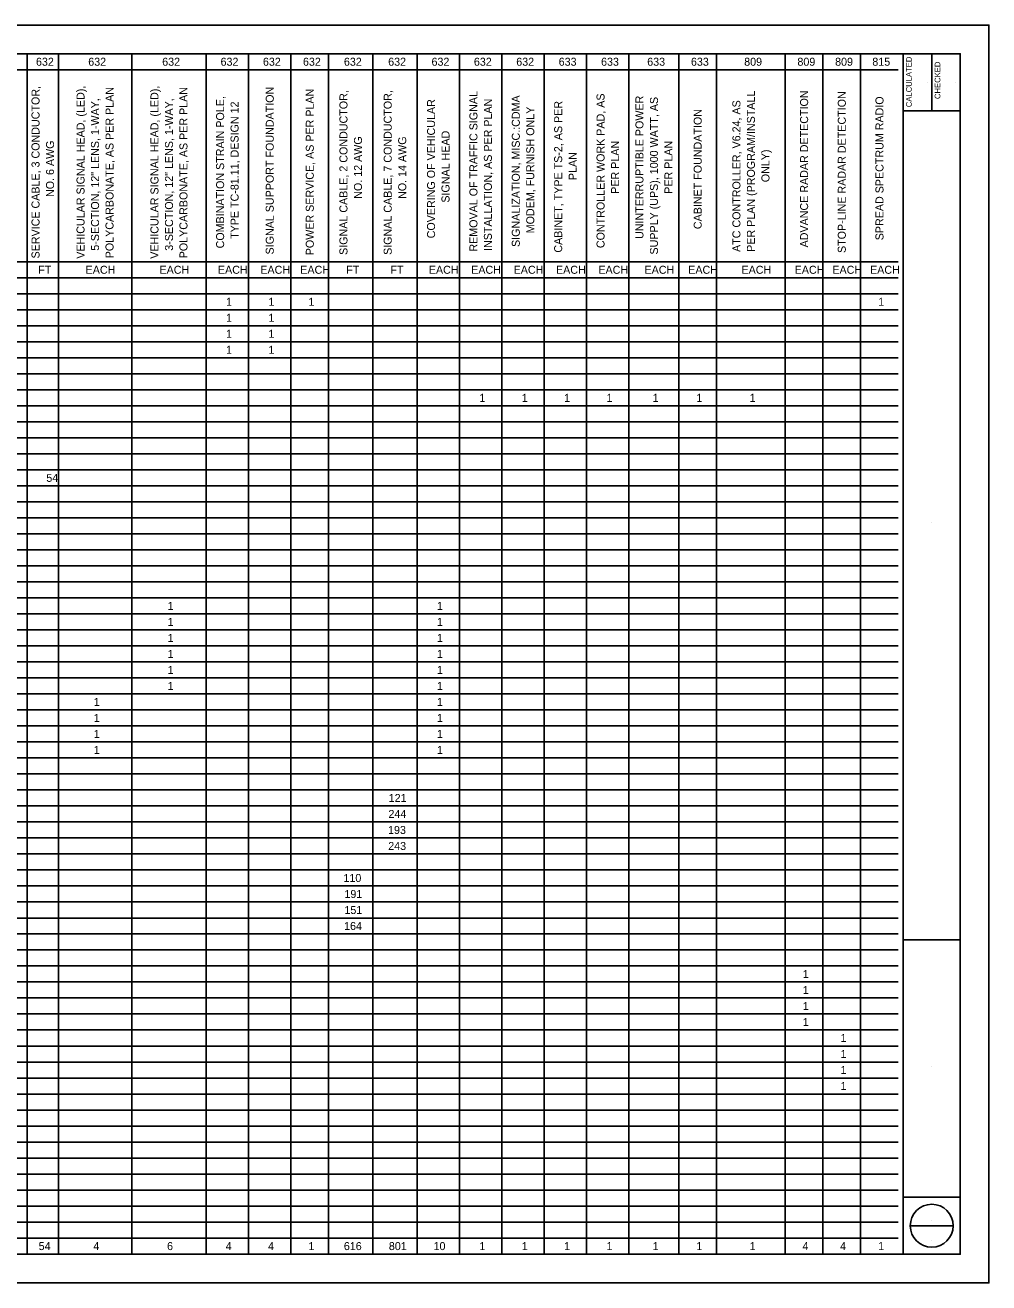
# Model space of a CAD drawing. Extents: x 43.5 to 77.5, y 34.1 to 56.1.
# Drawn here: x 60.61 to 77.46, y 34.09 to 56.09 of the extents above; entities that cross this region are included whole.
import ezdxf

# ---------------------------------------------------------------- set-up
doc = ezdxf.new("R2010")
doc.units = 0
for name, color, linetype in [('SH_Border', 7, 'Continuous'), ('SH_Cut_Line', 7, 'Continuous'), ('SH_Data', 7, 'Continuous'), ('SH_Text', 7, 'Continuous')]:
    doc.layers.add(name, color=color, linetype=linetype)

msp = doc.modelspace()

# ---------------------------------------------------------------- linework, layer by layer
at = {"layer": 'SH_Border'}
for p, q in [((45.459, 55.586), (75.875, 55.586)), ((60.642, 55.586), (60.642, 34.589)), ((61.186, 55.586), (61.186, 34.589)), ((62.47, 55.586), (62.47, 34.589)), ((63.771, 55.586), (63.771, 34.589)), ((64.512, 55.586), (64.512, 34.589)), ((65.253, 55.586), (65.253, 34.589)), ((65.912, 55.586), (65.912, 34.589)), ((66.686, 55.586), (66.686, 34.589)), ((67.46, 55.586), (67.46, 34.589)), ((68.201, 55.586), (68.201, 34.589)), ((68.942, 55.586), (68.942, 34.589)), ((69.683, 55.586), (69.683, 34.589)), ((70.424, 55.586), (70.424, 34.589)), ((71.165, 55.586), (71.165, 34.589)), ((72.038, 55.586), (72.038, 34.589)), ((72.697, 55.586), (72.697, 34.589)), ((73.899, 55.586), (73.899, 34.589)), ((74.558, 55.586), (74.558, 34.589)), ((75.216, 55.586), (75.216, 34.589)), ((75.959, 34.586), (75.959, 55.586)), ((76.459, 55.586), (76.459, 54.586)), ((52.029, 55.306), (75.875, 55.306)), ((75.959, 54.586), (76.959, 54.586)), ((52.029, 51.947), (75.875, 51.947)), ((45.459, 51.667), (75.875, 51.667)), ((45.459, 51.387), (75.875, 51.387)), ((45.459, 51.107), (75.875, 51.107)), ((45.459, 50.827), (75.875, 50.827)), ((45.459, 50.547), (75.875, 50.547)), ((45.459, 50.267), (75.875, 50.267)), ((45.459, 49.987), (75.875, 49.987)), ((45.459, 49.707), (75.875, 49.707)), ((45.459, 49.427), (75.875, 49.427)), ((45.459, 49.147), (75.875, 49.147)), ((45.459, 48.867), (75.875, 48.867)), ((45.459, 48.587), (75.875, 48.587)), ((45.459, 48.307), (75.875, 48.307)), ((45.459, 48.027), (75.875, 48.027)), ((45.459, 47.747), (75.875, 47.747)), ((45.459, 47.467), (75.875, 47.467)), ((45.459, 47.187), (75.875, 47.187)), ((45.459, 46.908), (75.875, 46.908)), ((45.459, 46.628), (75.875, 46.628)), ((45.459, 46.348), (75.875, 46.348)), ((45.459, 46.068), (75.875, 46.068)), ((45.459, 45.788), (75.875, 45.788)), ((45.459, 45.508), (75.875, 45.508)), ((45.459, 45.228), (75.875, 45.228)), ((45.459, 44.948), (75.875, 44.948)), ((45.459, 44.668), (75.875, 44.668)), ((45.459, 44.388), (75.875, 44.388)), ((45.459, 44.108), (75.875, 44.108)), ((45.459, 43.828), (75.875, 43.828)), ((45.459, 43.548), (75.875, 43.548)), ((45.459, 43.268), (75.875, 43.268)), ((45.459, 42.988), (75.875, 42.988)), ((45.459, 42.708), (75.875, 42.708)), ((45.459, 42.428), (75.875, 42.428)), ((45.459, 42.148), (75.875, 42.148)), ((45.459, 41.868), (75.875, 41.868)), ((45.459, 41.588), (75.875, 41.588)), ((45.459, 41.308), (75.875, 41.308)), ((45.459, 41.028), (75.875, 41.028)), ((45.459, 40.748), (75.875, 40.748)), ((45.459, 40.468), (75.875, 40.468)), ((45.459, 40.189), (75.875, 40.189)), ((75.959, 40.086), (76.959, 40.086)), ((45.459, 39.909), (75.875, 39.909)), ((45.459, 39.629), (75.875, 39.629)), ((45.459, 39.349), (75.875, 39.349)), ((45.459, 39.069), (75.875, 39.069)), ((45.459, 38.789), (75.875, 38.789)), ((45.459, 38.509), (75.875, 38.509)), ((45.459, 38.229), (75.875, 38.229)), ((45.459, 37.949), (75.875, 37.949)), ((45.459, 37.669), (75.875, 37.669)), ((45.459, 37.389), (75.875, 37.389)), ((45.459, 37.109), (75.875, 37.109)), ((45.459, 36.829), (75.875, 36.829)), ((45.459, 36.549), (75.875, 36.549)), ((45.459, 36.269), (75.875, 36.269)), ((45.459, 35.989), (75.875, 35.989)), ((45.459, 35.709), (75.875, 35.709)), ((45.459, 35.429), (75.875, 35.429)), ((75.959, 35.586), (76.959, 35.586)), ((45.459, 35.149), (75.875, 35.149)), ((45.459, 34.869), (75.875, 34.869)), ((45.459, 34.589), (75.875, 34.589))]:
    msp.add_line(p, q, dxfattribs=at)
msp.add_lwpolyline([(45.459, 55.586), (76.959, 55.586), (76.959, 34.586), (45.459, 34.586)], close=True, dxfattribs=at)
at = {"layer": 'SH_Cut_Line'}
msp.add_lwpolyline([(43.459, 34.086), (77.459, 34.086), (77.459, 56.086), (43.459, 56.086)], close=True, dxfattribs=at)
at = {"layer": 'SH_Data'}
for p, q in [((76.379, 55.09), (76.379, 55.09)), ((76.879, 55.09), (76.879, 55.09)), ((76.459, 47.378), (76.459, 47.378)), ((76.459, 37.878), (76.459, 37.878)), ((76.084, 35.086), (76.834, 35.086)), ((76.459, 35.171), (76.459, 35.171)), ((76.459, 34.831), (76.459, 34.831))]:
    msp.add_line(p, q, dxfattribs=at)
msp.add_circle((76.459, 35.086), 0.375, dxfattribs=at)

# ---------------------------------------------------------------- texts
for s, p in [('CALCULATED', (76.111, 54.651)), ('CHECKED', (76.611, 54.794))]:
    msp.add_text(s, height=0.1, rotation=90, dxfattribs=at).set_placement(p)
at = {"layer": 'SH_Text'}
for s, p in [('632', (60.795, 55.376)), ('632', (61.709, 55.376)), ('632', (63.002, 55.376)), ('632', (64.023, 55.376)), ('632', (64.764, 55.376)), ('632', (65.464, 55.376)), ('632', (66.18, 55.376)), ('632', (66.954, 55.376)), ('632', (67.712, 55.376)), ('632', (68.453, 55.376)), ('632', (69.194, 55.376)), ('633', (69.936, 55.376)), ('633', (70.677, 55.376)), ('633', (71.484, 55.376)), ('633', (72.249, 55.376)), ('809', (73.18, 55.376)), ('809', (74.111, 55.376)), ('809', (74.77, 55.376)), ('815', (75.421, 55.376)), ('FT', (60.835, 51.737)), ('EACH', (61.663, 51.737)), ('EACH', (62.955, 51.737)), ('EACH', (63.977, 51.737)), ('EACH', (64.718, 51.737)), ('EACH', (65.417, 51.737)), ('FT', (66.22, 51.737)), ('FT', (66.994, 51.737)), ('EACH', (67.665, 51.737)), ('EACH', (68.406, 51.737)), ('EACH', (69.148, 51.737)), ('EACH', (69.889, 51.737)), ('EACH', (70.63, 51.737)), ('EACH', (71.437, 51.737)), ('EACH', (72.202, 51.737)), ('EACH', (73.133, 51.737)), ('EACH', (74.063, 51.737)), ('EACH', (74.722, 51.737)), ('EACH', (75.381, 51.737)), ('1', (64.119, 51.177)), ('1', (64.86, 51.177)), ('1', (65.56, 51.177)), ('1', (75.523, 51.177)), ('1', (64.119, 50.897)), ('1', (64.86, 50.897)), ('1', (64.119, 50.617)), ('1', (64.86, 50.617)), ('1', (64.119, 50.337)), ('1', (64.86, 50.337)), ('1', (68.549, 49.497)), ('1', (69.29, 49.497)), ('1', (70.031, 49.497)), ('1', (70.772, 49.497)), ('1', (71.579, 49.497)), ('1', (72.344, 49.497)), ('1', (73.275, 49.497)), ('54', (60.976, 48.097)), ('1', (63.098, 45.858)), ('1', (67.807, 45.858)), ('1', (63.098, 45.578)), ('1', (67.807, 45.578)), ('1', (63.098, 45.298)), ('1', (67.807, 45.298)), ('1', (63.098, 45.018)), ('1', (67.807, 45.018)), ('1', (63.098, 44.738)), ('1', (67.807, 44.738)), ('1', (63.098, 44.458)), ('1', (67.807, 44.458)), ('1', (61.805, 44.178)), ('1', (67.807, 44.178)), ('1', (61.805, 43.898)), ('1', (67.807, 43.898)), ('1', (61.805, 43.618)), ('1', (67.807, 43.618)), ('1', (61.805, 43.338)), ('1', (67.807, 43.338)), ('121', (66.963, 42.498)), ('244', (66.959, 42.218)), ('193', (66.952, 41.938)), ('243', (66.955, 41.658)), ('110', (66.172, 41.098)), ('191', (66.189, 40.818)), ('151', (66.189, 40.538)), ('164', (66.183, 40.258)), ('1', (74.205, 39.419)), ('1', (74.205, 39.139)), ('1', (74.205, 38.859)), ('1', (74.205, 38.579)), ('1', (74.864, 38.299)), ('1', (74.864, 38.019)), ('1', (74.864, 37.739)), ('1', (74.864, 37.459)), ('54', (60.842, 34.659)), ('4', (61.798, 34.659)), ('6', (63.087, 34.659)), ('4', (64.112, 34.659)), ('4', (64.853, 34.659)), ('1', (65.56, 34.659)), ('616', (66.179, 34.659)), ('801', (66.966, 34.659)), ('10', (67.748, 34.659)), ('1', (68.549, 34.659)), ('1', (69.29, 34.659)), ('1', (70.031, 34.659)), ('1', (70.772, 34.659)), ('1', (71.579, 34.659)), ('1', (72.344, 34.659)), ('1', (73.275, 34.659)), ('4', (74.199, 34.659)), ('4', (74.857, 34.659)), ('1', (75.523, 34.659))]:
    msp.add_text(s, height=0.14, dxfattribs=at).set_placement(p)
for s, p in [('SERVICE CABLE, 3 CONDUCTOR, ', (60.857, 52.005)), ('VEHICULAR SIGNAL HEAD, (LED), ', (61.644, 52)), ('VEHICULAR SIGNAL HEAD, (LED), ', (62.937, 52)), ('5-SECTION, 12" LENS, 1-WAY, ', (61.898, 52.141)), ('POLYCARBONATE, AS PER PLAN', (62.151, 52.008)), ('3-SECTION, 12" LENS, 1-WAY, ', (63.191, 52.14)), ('POLYCARBONATE, AS PER PLAN', (63.444, 52.008)), ('COMBINATION STRAIN POLE, ', (64.085, 52.181)), ('SIGNAL SUPPORT FOUNDATION', (64.953, 52.075)), ('POWER SERVICE, AS PER PLAN', (65.653, 52.061)), ('SIGNAL CABLE, 2 CONDUCTOR, ', (66.242, 52.067)), ('SIGNAL CABLE, 7 CONDUCTOR, ', (67.016, 52.067)), ('COVERING OF VEHICULAR ', (67.774, 52.357)), ('REMOVAL OF TRAFFIC SIGNAL ', (68.515, 52.125)), ('INSTALLATION, AS PER PLAN', (68.768, 52.136)), ('SIGNALIZATION, MISC.:CDMA ', (69.256, 52.206)), ('CONTROLLER WORK PAD, AS ', (70.738, 52.186)), ('UNINTERRUPTIBLE POWER ', (71.418, 52.346)), ('SUPPLY (UPS), 1000 WATT, AS ', (71.672, 52.074)), ('PER PLAN (PROGRAM/INSTALL ', (73.368, 52.121)), ('ADVANCE RADAR DETECTION', (74.298, 52.198)), ('STOP-LINE RADAR DETECTION', (74.957, 52.1)), ('SPREAD SPECTRUM RADIO', (75.616, 52.323)), ('TYPE TC-81.11, DESIGN 12', (64.338, 52.347)), ('MODEM, FURNISH ONLY', (69.509, 52.445)), ('CABINET, TYPE TS-2, AS PER ', (69.997, 52.107)), ('CABINET FOUNDATION', (72.437, 52.518)), ('ATC CONTROLLER, V6.24, AS ', (73.114, 52.119)), ('NO. 12 AWG', (66.496, 53.049)), ('NO. 14 AWG', (67.27, 53.047)), ('SIGNAL HEAD', (68.027, 52.981)), ('NO. 6 AWG', (61.111, 53.08)), ('PER PLAN', (70.992, 53.137)), ('PER PLAN', (71.925, 53.137)), ('PLAN', (70.251, 53.376)), ('ONLY)', (73.622, 53.339))]:
    msp.add_text(s, height=0.14, rotation=90, dxfattribs=at).set_placement(p)

doc.saveas('drawing.dxf')
